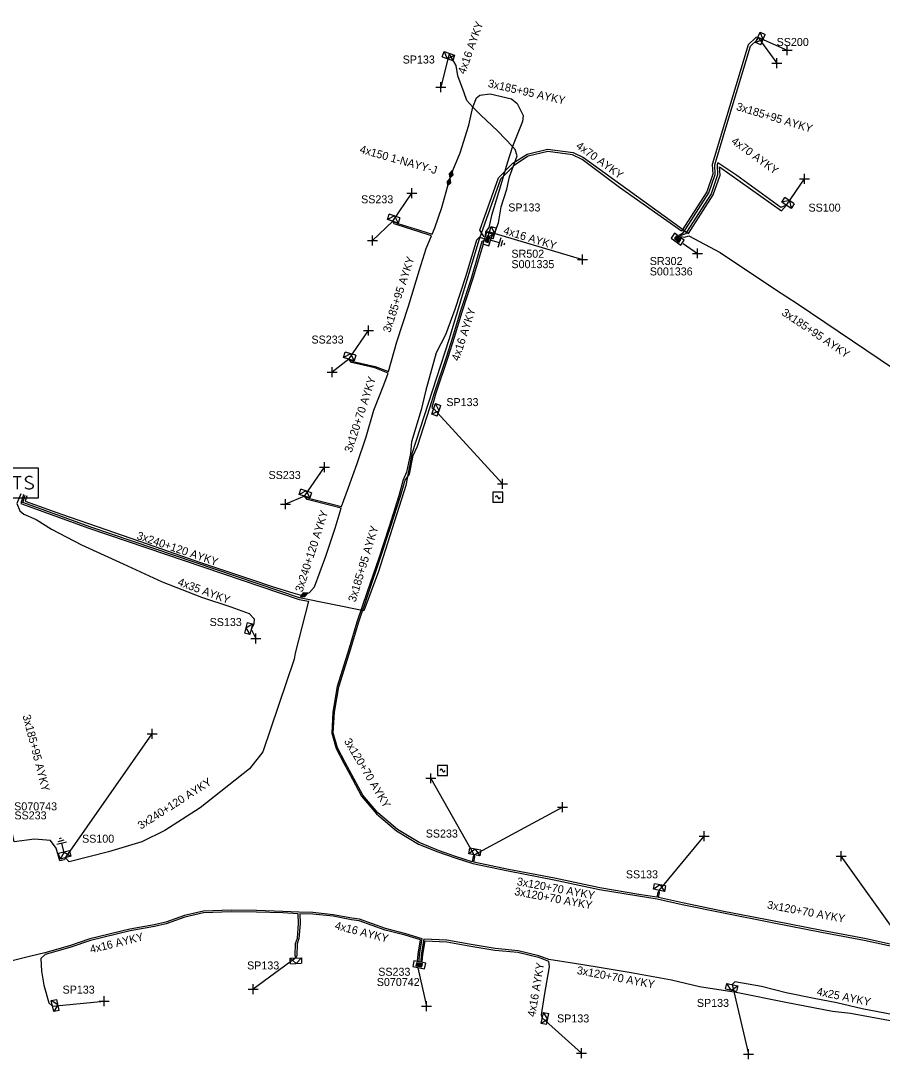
# Model space of a CAD drawing. Extents: x -763093 to -760976, y -1155572 to -1152009.
# Drawn here: x -762090.2 to -761982.6, y -1154578.9 to -1154449.2 of the extents above; entities that cross this region are included whole.
import ezdxf

# ---------------------------------------------------------------- set-up
doc = ezdxf.new("R2010")
doc.units = 0
for name, color, linetype in [('Vrstva 1', 7, 'Continuous'), ('Vrstva 14', 7, 'Continuous'), ('Vrstva 15', 7, 'Continuous'), ('Vrstva 19', 7, 'Continuous'), ('Vrstva 25', 7, 'Continuous'), ('Vrstva 28', 7, 'Continuous'), ('Vrstva 29', 7, 'Continuous'), ('Vrstva 30', 7, 'Continuous'), ('Vrstva 31', 7, 'Continuous'), ('Vrstva 33', 7, 'Continuous'), ('Vrstva 34', 7, 'Continuous'), ('Vrstva 4', 7, 'Continuous'), ('Vrstva 5', 7, 'Continuous'), ('Vrstva 59', 7, 'Continuous'), ('Vrstva 6', 7, 'Continuous'), ('Vrstva 8', 7, 'Continuous'), ('Vrstva 9', 7, 'Continuous')]:
    doc.layers.add(name, color=color, linetype=linetype)

# ---------------------------------------------------------------- blocks, each defined once
blk = doc.blocks.new('NN870')
at = {"layer": 'Vrstva 4'}
for points in [[(0, -0.25), (0.5, 0), (0, 0.25), (-0.5, 0), (0, -0.25)], [(0.37, 0), (0, 0.19), (-0.36, 0), (0, -0.19), (0.37, 0)], [(0.24, 0), (0, 0.12), (-0.25, 0), (0, -0.12), (0.24, 0)], [(0.12, 0), (0, 0.06), (-0.13, 0), (0, -0.06), (0.12, 0)]]:
    blk.add_lwpolyline(points, dxfattribs=at)
blk = doc.blocks.new('NN800')
at = {"layer": 'Vrstva 1'}
for points in [[(-0.44, 0.44), (0.44, -0.44)], [(-0.44, -0.44), (0.44, 0.44)]]:
    blk.add_lwpolyline(points, dxfattribs=at)
blk = doc.blocks.new('NN620')
at = {"layer": 'Vrstva 8'}
for points in [[(0.75, 0), (-0.75, 0)], [(-0.75, 0), (-0.75, -0.75)], [(0.75, -0.75), (0.75, 0)], [(-0.75, -0.75), (0.75, -0.75)], [(0.37, -0.18), (-0.38, -0.18)], [(-0.38, -0.18), (-0.38, -0.56)], [(-0.38, -0.56), (0.37, -0.56)], [(0.32, -0.23), (-0.33, -0.23)], [(-0.33, -0.23), (-0.33, -0.51)], [(-0.33, -0.51), (0.32, -0.51)], [(0.27, -0.27), (-0.28, -0.27)], [(-0.28, -0.27), (-0.28, -0.46)], [(-0.28, -0.46), (0.27, -0.46)], [(0.23, -0.32), (-0.23, -0.32)], [(-0.23, -0.32), (-0.23, -0.42)], [(-0.23, -0.42), (0.23, -0.42)], [(-0.19, -0.37), (0.19, -0.37)], [(0.23, -0.42), (0.23, -0.32)], [(0.27, -0.46), (0.27, -0.27)], [(0.32, -0.51), (0.32, -0.23)], [(0.37, -0.56), (0.37, -0.18)]]:
    blk.add_lwpolyline(points, dxfattribs=at)
blk = doc.blocks.new('NN630')
at = {"layer": 'Vrstva 9'}
for points in [[(0, -0.7), (-0.7, 0)], [(-0.7, -0.7), (-0.7, 0), (0.7, 0), (0.7, -0.7)], [(-0.7, -0.7), (0.7, -0.7)], [(0, -0.7), (0.7, 0)]]:
    blk.add_lwpolyline(points, dxfattribs=at)
blk = doc.blocks.new('NN810')
at = {"layer": 'Vrstva 14'}
for points in [[(0, -0.64), (0, -1.89)], [(0.63, -1.89), (-0.62, -1.89)], [(0.39, -2.2), (-0.4, -2.2)], [(0, -2.52), (-0.12, -2.52)], [(0.14, -2.52), (0, -2.52)]]:
    blk.add_lwpolyline(points, dxfattribs=at)
blk = doc.blocks.new('NN740')
at = {"layer": 'Vrstva 1'}
for points in [[(0.62, 0.62), (-0.63, 0.62)], [(-0.63, 0.62), (-0.63, -0.63)], [(0, 0), (0, 0.01), (0, 0.03), (-0.01, 0.05), (-0.01, 0.06), (-0.02, 0.08), (-0.03, 0.09), (-0.04, 0.1), (-0.05, 0.11), (-0.06, 0.12), (-0.08, 0.13), (-0.09, 0.14), (-0.11, 0.14), (-0.12, 0.15), (-0.14, 0.15), (-0.15, 0.15), (-0.17, 0.15), (-0.18, 0.15), (-0.2, 0.15), (-0.21, 0.14), (-0.23, 0.13), (-0.24, 0.12), (-0.26, 0.11), (-0.27, 0.1), (-0.28, 0.09), (-0.29, 0.08), (-0.29, 0.06), (-0.3, 0.05), (-0.3, 0.03), (-0.31, 0.02), (-0.31, 0), (-0.31, 0)], [(0.62, -0.63), (0.62, 0.62)], [(-0.63, -0.63), (0.62, -0.63)], [(0, 0), (0, -0.02), (0, -0.03), (0.01, -0.05), (0.01, -0.06), (0.02, -0.08), (0.03, -0.09), (0.04, -0.1), (0.05, -0.11), (0.06, -0.12), (0.07, -0.13), (0.09, -0.14), (0.1, -0.15), (0.12, -0.15), (0.13, -0.15), (0.15, -0.15), (0.16, -0.15), (0.18, -0.15), (0.19, -0.15), (0.21, -0.14), (0.22, -0.14), (0.24, -0.13), (0.25, -0.12), (0.26, -0.11), (0.27, -0.09), (0.28, -0.08), (0.29, -0.07), (0.29, -0.05), (0.3, -0.04), (0.3, -0.02), (0.3, -0.01), (0.3, -0.01)]]:
    blk.add_lwpolyline(points, dxfattribs=at)
blk = doc.blocks.new('NN640')
at = {"layer": 'Vrstva 6'}
for points in [[(-1.89, 1.89), (1.89, 1.89)], [(-1.89, -1.89), (-1.89, 1.89)], [(1.89, 1.89), (1.89, -1.89)], [(-1.26, 0.79), (-0.22, 0.79)], [(-0.73, 0.79), (-0.73, -0.79)], [(1.2, 0.66), (0.94, 0.79), (0.66, 0.79), (0.41, 0.66), (0.28, 0.47), (0.28, 0.41), (0.41, 0.22), (1.13, -0.16), (1.26, -0.32), (1.26, -0.47), (1.13, -0.66), (0.91, -0.79), (0.63, -0.79), (0.5, -0.73), (0.28, -0.6)], [(1.89, -1.89), (-1.89, -1.89)]]:
    blk.add_lwpolyline(points, dxfattribs=at)

msp = doc.modelspace()

# ---------------------------------------------------------------- linework, layer by layer
at = {"layer": 'Vrstva 5'}
for points in [[(-762007.92, -1154475.96), (-762007.39, -1154475.63), (-762004.2, -1154470.66), (-762003.42, -1154468.38), (-762003.48, -1154467.15), (-762001.84, -1154461.73), (-761999.03, -1154452.34), (-761998.15, -1154451.5), (-761998.09, -1154451.24), (-761998.33, -1154451.26), (-761999.29, -1154452.18), (-762003.79, -1154467.12), (-762003.72, -1154468.34), (-762004.47, -1154470.53), (-762007.64, -1154475.47), (-762015.37, -1154469.98), (-762020.03, -1154466.49), (-762021.26, -1154465.9), (-762024.34, -1154465.51), (-762026.79, -1154466.1), (-762028.49, -1154467.19), (-762030.22, -1154468.96), (-762032.89, -1154476.45), (-762036.68, -1154489.02), (-762041.31, -1154503.25), (-762042.08, -1154507.22), (-762045.47, -1154517.96), (-762047.3, -1154522.87), (-762055.34, -1154521.24), (-762081.42, -1154512.42), (-762089.9, -1154509.33), (-762089.63, -1154508.41)], [(-762031.32, -1154476.03), (-762031.11, -1154476.02), (-762030.5, -1154474.42), (-762030.14, -1154472.41), (-762029.44, -1154470.22), (-762029.1, -1154468.68), (-762028.14, -1154466.04), (-762028.41, -1154465.24), (-762028.76, -1154464.89), (-762030.56, -1154462.95), (-762032.73, -1154460.92), (-762033.68, -1154459.97), (-762034.44, -1154459.14), (-762034.76, -1154458.19), (-762035.57, -1154456.04), (-762035.77, -1154454.74), (-762036.63, -1154453.25)], [(-762036.41, -1154468.36), (-762035.26, -1154465.65), (-762034.2, -1154462.22), (-762033.68, -1154459.97), (-762033.25, -1154458.79), (-762032.82, -1154458.46), (-762031.52, -1154458.31), (-762028.87, -1154458.92), (-762028.16, -1154459.51), (-762027.39, -1154460.99), (-762027.48, -1154461.74), (-762028.76, -1154464.89), (-762029.39, -1154466.95), (-762030.18, -1154469.67), (-762031.38, -1154473.48), (-762031.71, -1154474.98), (-762032.13, -1154475.55), (-762032.17, -1154476.04)], [(-762032.28, -1154476.17), (-762032.81, -1154475.33), (-762030.48, -1154468.8), (-762028.68, -1154466.96), (-762026.91, -1154465.82), (-762024.36, -1154465.21), (-762021.17, -1154465.61), (-762019.87, -1154466.23), (-762007.82, -1154474.95), (-762006.99, -1154475.56)], [(-762006.99, -1154475.56), (-762006.74, -1154475.74), (-762003.66, -1154470.92), (-762002.82, -1154468.47), (-762002.87, -1154467.43), (-761995.15, -1154472.91), (-761994.52, -1154472.21), (-761995.23, -1154472.49), (-762000.71, -1154468.5), (-762003.09, -1154466.92), (-762003.18, -1154467.18), (-762003.12, -1154468.42), (-762003.93, -1154470.79), (-762006.99, -1154475.56)], [(-762036.68, -1154469.32), (-762036.41, -1154468.36)], [(-762049.17, -1154491.43), (-762048.64, -1154491.71), (-762045.88, -1154492.35), (-762044.21, -1154492.98), (-762043.2, -1154489.28), (-762041.71, -1154484.82), (-762040.37, -1154480.28), (-762039.51, -1154477.61), (-762038.87, -1154476.02), (-762040.4, -1154475.52), (-762043.14, -1154474.66), (-762043.54, -1154474.52), (-762043.69, -1154474.21), (-762043.06, -1154474.48), (-762040.34, -1154475.32), (-762038.79, -1154475.84), (-762038.45, -1154475.05), (-762037.58, -1154472.49), (-762036.68, -1154469.32)], [(-762032.3, -1154476.39), (-762032.88, -1154476.22), (-762033.25, -1154476.56), (-762034.58, -1154481.03), (-762035.93, -1154485.24), (-762037.09, -1154488.39), (-762038.26, -1154490.65), (-762039.57, -1154495.3), (-762040.15, -1154497.78), (-762041.36, -1154501.76), (-762041.5, -1154503.2), (-762041.97, -1154505.55), (-762042.4, -1154506.52), (-762042.94, -1154508.49), (-762044.16, -1154512.35), (-762045.44, -1154516.28), (-762046.88, -1154520.5), (-762048.19, -1154524.29), (-762049.13, -1154527.53), (-762050.62, -1154532.32), (-762051.18, -1154535.52), (-762051.32, -1154538.14), (-762050.77, -1154540.08), (-762049.81, -1154541.9), (-762048.73, -1154543.91), (-762047.6, -1154546.03), (-762045.72, -1154548.22), (-762043.23, -1154550.34), (-762040.5, -1154552), (-762038.05, -1154552.99), (-762035.92, -1154553.74), (-762033.7, -1154554.44), (-762029.3, -1154555.36), (-762023.55, -1154556.48), (-762017.87, -1154557.67), (-762012.99, -1154558.48), (-762010.65, -1154558.85), (-762007.55, -1154559.56), (-762002.39, -1154560.61), (-761996.08, -1154561.83), (-761990.15, -1154563.01), (-761984.81, -1154564.01), (-761980.77, -1154564.88)], [(-761980.83, -1154564.66), (-761984.77, -1154563.81), (-761990.11, -1154562.81), (-761996.04, -1154561.63), (-762002.35, -1154560.41), (-762007.51, -1154559.36), (-762010.51, -1154558.67), (-762010.39, -1154558.1), (-762010.44, -1154557.78), (-762010.6, -1154558.06), (-762010.71, -1154558.64), (-762012.95, -1154558.28), (-762017.83, -1154557.47), (-762023.51, -1154556.28), (-762029.26, -1154555.16), (-762033.57, -1154554.26), (-762033.46, -1154553.59), (-762033.52, -1154553.33), (-762033.65, -1154553.55), (-762033.76, -1154554.21), (-762035.86, -1154553.56), (-762037.97, -1154552.81), (-762040.4, -1154551.82), (-762043.11, -1154550.18), (-762045.58, -1154548.08), (-762047.44, -1154545.91), (-762048.55, -1154543.81), (-762049.63, -1154541.8), (-762050.59, -1154540), (-762051.12, -1154538.12), (-762050.98, -1154535.54), (-762050.42, -1154532.36), (-762048.93, -1154527.59), (-762047.99, -1154524.35), (-762046.7, -1154520.56), (-762045.26, -1154516.34), (-762043.97, -1154512.42), (-762042.72, -1154508.55), (-762042.14, -1154506.55), (-762041.6, -1154505.82), (-762041.15, -1154503.45), (-762040.61, -1154502.29), (-762039.01, -1154497.38), (-762038.5, -1154495.64), (-762037, -1154491.17), (-762036.2, -1154488.67), (-762035.24, -1154485.5), (-762033.87, -1154481.31), (-762032.54, -1154476.68), (-762032.3, -1154476.61)], [(-762031.9, -1154475.65), (-762031.8, -1154475.48), (-762031.6, -1154475.54)], [(-762006.99, -1154475.56), (-762007.14, -1154475.79), (-762007.81, -1154476.03)], [(-762007.71, -1154476.11), (-762007.25, -1154476.2), (-762006.72, -1154476.02), (-762002.79, -1154478.1), (-761995.78, -1154482.81), (-761993.17, -1154484.48), (-761981.15, -1154492.59), (-761975.11, -1154496.45), (-761966.77, -1154501.61), (-761959.89, -1154505.09), (-761960.15, -1154505.52), (-761960.09, -1154505.71)], [(-762032.42, -1154477.09), (-762033.68, -1154481.37), (-762035.05, -1154485.56), (-762036.01, -1154488.73), (-762036.81, -1154491.23), (-762038.31, -1154495.7), (-762038.83, -1154497.49), (-762038.58, -1154497.66)], [(-762054.72, -1154508.56), (-762054.23, -1154508.79), (-762051.38, -1154509.5), (-762050.09, -1154509.84), (-762049.21, -1154507.47), (-762048.13, -1154504.45), (-762047, -1154501.12), (-762046.06, -1154497.79), (-762044.82, -1154494.64), (-762044.27, -1154493.17), (-762045.94, -1154492.53), (-762048.86, -1154491.85), (-762049.17, -1154491.43)], [(-762090.16, -1154508.24), (-762090.66, -1154509.47), (-762090.26, -1154510.39), (-762089.78, -1154510.78), (-762088.25, -1154511.46), (-762086.33, -1154512.65), (-762082.58, -1154514.63), (-762077.38, -1154517.01), (-762072.49, -1154519.24), (-762067.59, -1154521.18), (-762063.92, -1154522.37), (-762061.62, -1154523.2), (-762061.02, -1154523.88), (-762061.06, -1154524.55), (-762061.38, -1154525.16)], [(-762089.83, -1154508.35), (-762090.14, -1154509.45), (-762081.64, -1154512.55), (-762055.4, -1154521.44), (-762054.22, -1154521.68), (-762055.89, -1154528.15), (-762056.02, -1154528.89), (-762059.92, -1154540.47), (-762061.6, -1154542.62), (-762067.76, -1154547.48), (-762072.18, -1154550.3), (-762075.03, -1154551.71), (-762079.2, -1154552.97), (-762084.11, -1154554.2), (-762084.58, -1154553.7)], [(-762089.41, -1154508.49), (-762089.62, -1154509.16), (-762085.07, -1154510.81), (-762079.54, -1154512.71), (-762073.4, -1154514.82), (-762067.72, -1154516.82), (-762061.36, -1154518.97), (-762058.74, -1154519.82), (-762056.19, -1154520.63), (-762055, -1154520.96), (-762054.77, -1154520.86)], [(-762054.77, -1154520.86), (-762054.09, -1154520.57), (-762053.47, -1154519.88), (-762052.04, -1154516.06), (-762050.87, -1154512.55), (-762050.15, -1154510.03), (-762051.44, -1154509.7), (-762054.38, -1154508.97), (-762054.72, -1154508.56)], [(-762084.58, -1154553.7), (-762084.71, -1154553.99), (-762085.27, -1154554.08), (-762085.73, -1154552.51), (-762086.45, -1154551.57), (-762088.44, -1154551.39), (-762090.99, -1154551.71), (-762091.42, -1154549.75)], [(-762040.41, -1154566.61), (-762040.34, -1154565.8), (-762040.01, -1154563.84), (-762042.08, -1154563.2), (-762044.59, -1154562.54), (-762047.87, -1154561.4), (-762048.8, -1154561.26), (-762051.14, -1154560.82), (-762053.68, -1154560.54), (-762055.42, -1154560.5), (-762057.41, -1154560.41), (-762060.71, -1154560.31), (-762063.87, -1154560.26), (-762067.35, -1154560.37), (-762069.71, -1154560.93), (-762072.06, -1154561.76), (-762073.5, -1154562.09), (-762076.54, -1154562.63), (-762081.53, -1154563.83), (-762084.09, -1154564.7), (-762087.17, -1154565.6), (-762089.05, -1154566.03), (-762092.57, -1154566.93)], [(-762040.61, -1154566.58), (-762040.54, -1154565.77), (-762040.24, -1154563.98), (-762042.14, -1154563.4), (-762044.65, -1154562.74), (-762047.91, -1154561.6), (-762048.84, -1154561.46), (-762051.16, -1154561.02), (-762053.7, -1154560.74), (-762055.32, -1154560.7), (-762055.27, -1154561.93), (-762055.41, -1154563.78), (-762055.65, -1154564.47), (-762055.69, -1154565.94), (-762055.8, -1154566.22), (-762055.89, -1154565.93), (-762055.85, -1154564.43), (-762055.61, -1154563.74), (-762055.47, -1154561.93), (-762055.52, -1154560.7), (-762057.41, -1154560.61), (-762060.71, -1154560.51), (-762063.87, -1154560.46), (-762067.33, -1154560.57), (-762069.65, -1154561.13), (-762072, -1154561.96), (-762073.46, -1154562.29), (-762076.5, -1154562.83), (-762081.47, -1154564.03), (-762084.03, -1154564.9), (-762087.11, -1154565.8), (-762087.67, -1154566.28), (-762087.57, -1154567.88), (-762087.27, -1154569.63), (-762086.66, -1154571.84), (-762086.2, -1154572.24)], [(-761974.38, -1154575.21), (-761975.57, -1154575.22), (-761977.98, -1154574.71), (-761981.77, -1154574.02), (-761986.54, -1154573.16), (-761988.76, -1154572.92), (-761994.59, -1154571.8), (-762000.81, -1154570.53), (-762005.39, -1154569.85), (-762008.86, -1154569), (-762013.93, -1154568.1), (-762018.18, -1154567.38), (-762021, -1154566.93), (-762024.2, -1154566.41), (-762025.44, -1154565.94), (-762028.04, -1154565.32), (-762030.92, -1154565.04), (-762034.15, -1154564.5), (-762036.93, -1154564.01), (-762039.81, -1154563.88), (-762040.14, -1154565.82), (-762040.21, -1154566.65)], [(-762040.01, -1154566.67), (-762039.94, -1154565.85), (-762039.64, -1154564.08), (-762036.95, -1154564.21), (-762034.19, -1154564.7), (-762030.94, -1154565.24), (-762028.08, -1154565.52), (-762025.5, -1154566.14), (-762024.23, -1154566.61), (-762024.14, -1154567.34), (-762024.8, -1154570.93), (-762025.14, -1154573.35), (-762025.03, -1154573.71)], [(-761973.76, -1154575.05), (-761973.74, -1154574.68), (-761975.59, -1154574.34), (-761981.14, -1154573.34), (-761985.05, -1154572.56), (-761988.24, -1154571.84), (-761991.06, -1154571.28), (-761994.54, -1154570.59), (-761997.64, -1154569.8), (-762000.98, -1154569.21), (-762001.29, -1154569.55)]]:
    msp.add_lwpolyline(points, dxfattribs=at)
at = {"layer": 'Vrstva 59'}
for points in [[(-761998.09, -1154451.24), (-761995.71, -1154454.46)], [(-761998.09, -1154451.24), (-761994.42, -1154452.83)], [(-762036.63, -1154453.25), (-762037.69, -1154457.48)], [(-761994.52, -1154472.21), (-761992.27, -1154468.9)], [(-762043.69, -1154474.21), (-762041.33, -1154470.69)], [(-762043.69, -1154474.21), (-762046.24, -1154476.63)], [(-762031.6, -1154475.54), (-762020, -1154479)], [(-762007.44, -1154477.01), (-762005.65, -1154478.22)], [(-762049.17, -1154491.43), (-762046.72, -1154487.85)], [(-762049.17, -1154491.43), (-762051.26, -1154493.08)], [(-762038.58, -1154497.66), (-762030, -1154507)], [(-762054.72, -1154508.56), (-762052.21, -1154504.93)], [(-762054.72, -1154508.56), (-762057.08, -1154509.53)], [(-762061.38, -1154525.16), (-762060.8, -1154526.32)], [(-762084.58, -1154553.7), (-762073.75, -1154538.25)], [(-762033.52, -1154553.33), (-762038.93, -1154543.79)], [(-762033.52, -1154553.33), (-762022.5, -1154547.38)], [(-762010.44, -1154557.78), (-762004.81, -1154551)], [(-761980.49, -1154563.59), (-761987.69, -1154553.5)], [(-762055.8, -1154566.22), (-762061.13, -1154570.13)], [(-762040.57, -1154567.44), (-762039.5, -1154572.25)], [(-762001.29, -1154569.55), (-761999.25, -1154578.25)], [(-762086.2, -1154572.24), (-762079.75, -1154571.63)], [(-762025.03, -1154573.71), (-762020.13, -1154578.13)]]:
    msp.add_lwpolyline(points, dxfattribs=at)

# ---------------------------------------------------------------- block references
at = {"layer": 'Vrstva 15'}
for p, rotation in [((-762032.2, -1154476.33), 73.03946110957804), ((-762084.58, -1154553.7), -165.7064416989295)]:
    msp.add_blockref('NN810', p, dxfattribs=dict(at, rotation=rotation))
at = {"layer": 'Vrstva 19'}
for p, rotation in [((-762036.68, -1154469.32), 71.19418250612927), ((-762036.41, -1154468.36), 72.51607407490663), ((-762054.77, -1154520.86), 23.98418357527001)]:
    msp.add_blockref('NN870', p, dxfattribs=dict(at, rotation=rotation))
at = {"layer": 'Vrstva 25'}
msp.add_blockref('NN640', (-762089.88, -1154506.89), dxfattribs=at)
at = {"layer": 'Vrstva 28'}
for p, rotation in [((-762032.2, -1154476.33), 72.19864717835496), ((-762007.89, -1154476.14), -35.57196660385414), ((-762040.32, -1154566.72), -11.227680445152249)]:
    msp.add_blockref('NN620', p, dxfattribs=dict(at, rotation=rotation))
at = {"layer": 'Vrstva 31'}
for p, rotation in [((-761998.09, -1154451.24), 66.50883888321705), ((-762036.63, -1154453.25), -19.57785562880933), ((-761994.52, -1154472.21), 145.78619163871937), ((-762043.69, -1154474.21), 161.02538566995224), ((-762031.6, -1154475.54), 72.19864717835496), ((-762049.17, -1154491.43), 163.50401101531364), ((-762038.58, -1154497.66), 72.04210279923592), ((-762054.72, -1154508.56), 161.90496935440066), ((-762061.38, -1154525.16), -103.61382912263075), ((-762084.58, -1154553.7), -165.70644171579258), ((-762033.52, -1154553.33), 169.88559520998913), ((-762010.44, -1154557.78), 169.12170000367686), ((-762055.8, -1154566.22), 2.038655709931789), ((-762001.29, -1154569.55), -11.718261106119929), ((-762086.2, -1154572.24), 102.70038887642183), ((-762025.03, -1154573.71), 78.08389722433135)]:
    msp.add_blockref('NN630', p, dxfattribs=dict(at, rotation=rotation))
at = {"layer": 'Vrstva 34'}
for p, rotation in [((-761994.42, -1154452.84), 45), ((-761995.71, -1154454.46), 45), ((-762037.69, -1154457.48), 45), ((-761992.27, -1154468.9), 44.99999995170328), ((-762041.33, -1154470.69), 45), ((-762046.24, -1154476.63), 44.99999995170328), ((-762005.65, -1154478.22), 45), ((-762020, -1154479), 45), ((-762046.72, -1154487.85), 44.99999995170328), ((-762051.26, -1154493.08), 45), ((-762052.21, -1154504.93), 45), ((-762030, -1154507), 45), ((-762057.08, -1154509.53), 44.99999995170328), ((-762060.8, -1154526.32), 45.00000009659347), ((-762073.75, -1154538.25), 45), ((-762038.93, -1154543.79), 45.00000009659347), ((-762022.5, -1154547.38), 45), ((-762004.81, -1154551), 45), ((-761987.69, -1154553.5), 44.99999995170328), ((-762061.13, -1154570.13), 45), ((-762079.75, -1154571.63), 45), ((-762039.5, -1154572.25), 45), ((-762020.13, -1154578.13), 45), ((-761999.25, -1154578.25), 45)]:
    msp.add_blockref('NN800', p, dxfattribs=dict(at, rotation=rotation))
for p in [(-762030.56, -1154508.68), (-762037.48, -1154542.81)]:
    msp.add_blockref('NN740', p, dxfattribs=at)

# ---------------------------------------------------------------- texts
at = {"layer": 'Vrstva 29'}
for s, p in [('S001335', (-762028.87, -1154480.07)), ('S001336', (-762011.59, -1154480.98)), ('S070743', (-762090.98, -1154547.79)), ('S070742', (-762045.69, -1154569.73))]:
    msp.add_text(s, height=1, dxfattribs=at).set_placement(p)
at = {"layer": 'Vrstva 30'}
for s, p in [('SR502', (-762028.87, -1154478.77)), ('SR302', (-762011.59, -1154479.68)), ('SS233', (-762090.95, -1154548.92)), ('SS233', (-762045.51, -1154568.45))]:
    msp.add_text(s, height=1, dxfattribs=at).set_placement(p)
at = {"layer": 'Vrstva 33'}
for s, p in [('SS200', (-761995.75, -1154452.32)), ('SP133', (-762042.46, -1154454.51)), ('SS233', (-762047.65, -1154471.97)), ('SP133', (-762029.27, -1154472.99)), ('SS100', (-761991.77, -1154473.01)), ('SS233', (-762053.85, -1154489.49)), ('SP133', (-762037, -1154497.3)), ('SS233', (-762059.21, -1154506.41)), ('SS133', (-762066.57, -1154524.77)), ('SS233', (-762039.58, -1154551.19)), ('SS100', (-762082.5, -1154551.83)), ('SS133', (-762014.58, -1154556.28)), ('SP133', (-762061.89, -1154567.66)), ('SP133', (-762084.94, -1154570.68)), ('SP133', (-762005.71, -1154572.34)), ('SP133', (-762023.17, -1154574.28))]:
    msp.add_text(s, height=1, dxfattribs=at).set_placement(p)
at = {"layer": 'Vrstva 6'}
for s, rotation, p in [('4x16 AYKY', 70.378, (-762034.67, -1154455.92)), ('3x185+95 AYKY', 347.036, (-762031.87, -1154457.43)), ('3x185+95 AYKY', 343.157, (-762000.87, -1154460.3)), ('4x150 1-NAYY-J', 344.184, (-762047.9, -1154465.64)), ('4x70 AYKY', 324.131, (-762020.9, -1154464.99)), ('4x70 AYKY', 323.984, (-762001.5, -1154464.41)), ('4x16 AYKY', 342.911, (-762029.96, -1154475.77)), ('3x185+95 AYKY', 72.003, (-762044.02, -1154488.19)), ('4x16 AYKY', 72.042, (-762035.44, -1154491.74)), ('3x185+95 AYKY', 325.99, (-761995.21, -1154485.85)), ('3x120+70 AYKY', 72.01, (-762048.83, -1154503.18)), ('3x240+120 AYKY', 72.235, (-762054.98, -1154520.61)), ('3x240+120 AYKY', 341.294, (-762075.75, -1154513.88)), ('3x185+95 AYKY', 73.01, (-762048.35, -1154521.85)), ('4x35 AYKY', 339.717, (-762070.65, -1154519.65)), ('3x185+95 AYKY', 284.502, (-762089.94, -1154535.97)), ('3x120+70 AYKY', 300.931, (-762049.82, -1154539.15)), ('3x240+120 AYKY', 32.538, (-762075.16, -1154550.21)), ('3x120+70 AYKY', 349.464, (-762028.25, -1154557.12)), ('3x120+70 AYKY', 349.463, (-762028.56, -1154558.36)), ('3x120+70 AYKY', 349.523, (-761996.99, -1154560.04)), ('4x16 AYKY', 345.515, (-762051, -1154562.6)), ('4x16 AYKY', 13.831, (-762081.39, -1154565.65)), ('4x16 AYKY', 80.327, (-762025.92, -1154573.64)), ('3x120+70 AYKY', 349.268, (-762020.76, -1154568.21)), ('4x25 AYKY', 348.34, (-761990.81, -1154570.85))]:
    msp.add_text(s, height=1, rotation=rotation, dxfattribs=at).set_placement(p)

doc.saveas('drawing.dxf')
